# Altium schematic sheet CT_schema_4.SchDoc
size 329 x 327 mm
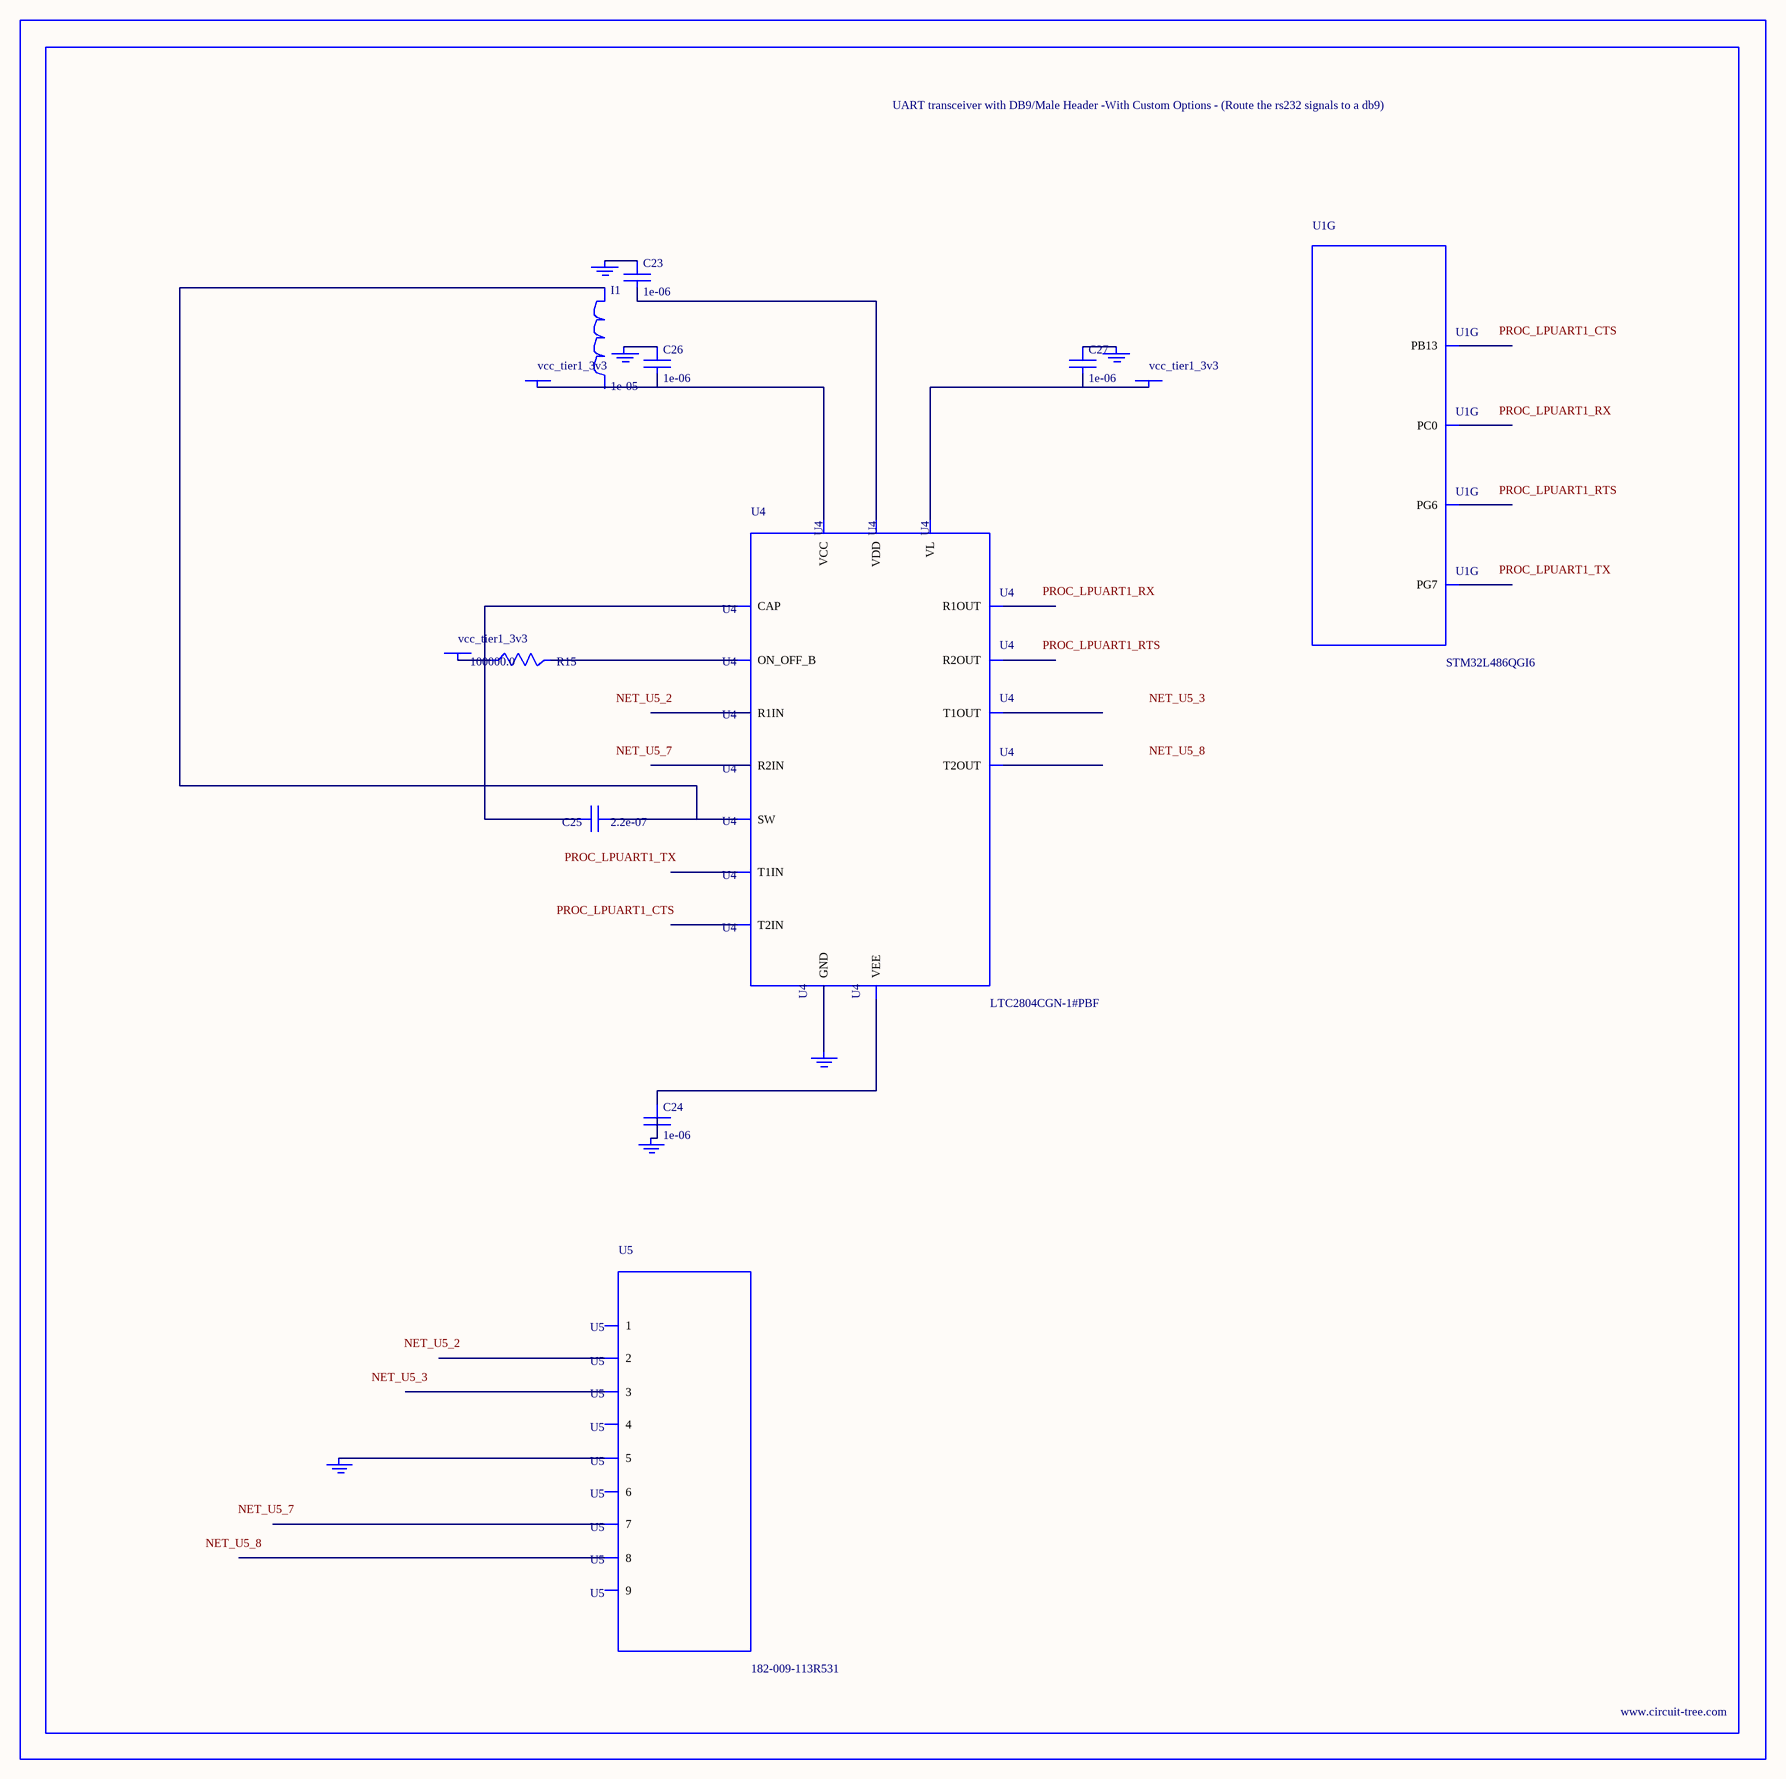
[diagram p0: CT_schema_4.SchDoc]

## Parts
BORDER3  (no value)
C23  1e-06  [C0603]
C24  1e-06  [C0603]
C25  2.2e-07  [C0603]
C26  1e-06  [C0603]
C27  1e-06  [C0603]
GND_INSTANCE_3_0  (no value)
GND_INSTANCE_3_1  (no value)
GND_INSTANCE_3_2  (no value)
GND_INSTANCE_3_3  (no value)
GND_INSTANCE_3_4  (no value)
GND_INSTANCE_3_5  (no value)
I1  1e-05  [L1210]
POWER_INSTANCE_3_0  vcc_tier1_3v3
POWER_INSTANCE_3_1  vcc_tier1_3v3
POWER_INSTANCE_3_2  vcc_tier1_3v3
R15  100000.0  [R0603]
U1  STM32L486QGI6  [UFBGA132]  (part G of 13)
U4  LTC2804CGN-1#PBF  [SSOP-16]
U5  182-009-113R531  [182-009-MALE]

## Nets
NetC23_1: C23.1 GND_INSTANCE_3_1.0(GND)
NetC23_2: C23.2 U4.6(VDD)
NetC24_1: C24.1 U4.9(VEE)
NetC24_2: C24.2 GND_INSTANCE_3_2.0(GND)
NetC25_1: C25.1 I1.1 U4.7(SW)
NetC25_2: C25.2 U4.10(CAP)
NetC26_1: C26.1 GND_INSTANCE_3_0.0(GND)
NetC26_2: C26.2 POWER_INSTANCE_3_0.0(PWR) U4.5(VCC)
NetC27_1: C27.1 GND_INSTANCE_3_3.0(GND)
NetC27_2: C27.2 POWER_INSTANCE_3_2.0(PWR) U4.12(VL)
NetGND_INSTANCE_3_4_0: GND_INSTANCE_3_4.0(GND) U4.8(GND)
NetGND_INSTANCE_3_5_0: GND_INSTANCE_3_5.0(GND) U5.5
NetPOWER_INSTANCE_3_1_0: POWER_INSTANCE_3_1.0(PWR) R15.1
NetR15_2: R15.2 U4.11(ON_OFF_B)

Not connected (* = marked no-connect by the designer): I1 2; U1 G4(PG6) H1(PC0) H4(PG7) K12(PB13); U4 1(R1IN) 2(R2IN) 3(T1OUT) 4(T2OUT) 13(T2IN) 14(T1IN) 15(R2OUT) 16(R1OUT); U5 1 2 3 4 6 7 8 9

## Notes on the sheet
- Labels drawn without touching a wire or pin: NET_U5_2, NET_U5_3, NET_U5_7, NET_U5_8, PROC_LPUART1_CTS, PROC_LPUART1_RTS, PROC_LPUART1_RX, PROC_LPUART1_TX

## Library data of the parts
BORDER3 = BORDER_PAGE3
C23 C24 C26 C27 = C0603C105K3RACTU
C25 = C0603C224K3RAC
GND_INSTANCE_3_0-GND_INSTANCE_3_5 = GND
I1 = CBC3225T100MR
POWER_INSTANCE_3_0-POWER_INSTANCE_3_2 = PWR
R15 = RC0603JR-07100KL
